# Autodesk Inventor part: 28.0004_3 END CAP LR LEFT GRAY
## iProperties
Created: 2007-04
Part Number: 28.0004_3 END CAP LR LEFT GRAY
Document SubType Name: Modeling
Designer: Andy Moles
Material: ABS Plastic
Mass: 17.1371 g
Surface Area: 77.8637 cm^2
Volume: 16.1671 cm^3
Density: 1.06 g/cm^3
Author: Andy Moles
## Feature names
1. Base1
